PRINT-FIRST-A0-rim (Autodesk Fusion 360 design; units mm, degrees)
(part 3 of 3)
extrude "Extrude2" cut sketch "E Rear Bearing Cap Bolt seed" profile of C1 along normal blind 3 (= "capThickness")
circular_pattern "C-Pattern1" TotalAngle 360
chamfer "Chamfer1" distance 0.3 (= "bedRelief")
work_plane "WorkPlane1" AlongDistance -29 (= "hubFace - adapterThickness") ExtraOffset 0
sketch "F Adapter Flange sketch" plane through (-20.5061, -20.5061, 0) normal (0.7071, 0.7071, 0) x axis (0, 0, 1)
  circle C1 centre (0, 0) radius 38
  dimension "d967" diameter C1 = 76 (= "mountOD")
extrude "Extrude1" new body sketch "F Adapter Flange sketch" along normal blind 6 (= "adapterThickness")
work_plane "WorkPlane2" AlongDistance -23 (= "hubFace") ExtraOffset 0
sketch "F Centering Pilot sketch" plane through (-16.2635, -16.2635, 0) normal (0.7071, 0.7071, 0) x axis (0, 0, 1)
  circle C1 centre (0, 0) radius 25
  circle C2 centre (0, 0) radius 17
  dimension "d972" diameter C1 = 50 (= "pilotDiameter")
  dimension "d973" diameter C2 = 34 (= "pilotInside")
extrude "Extrude2" add sketch "F Centering Pilot sketch" along normal blind 2 (= "pilotHeight")
work_plane "WorkPlane3" AlongDistance -29 (= "hubFace - adapterThickness") ExtraOffset 0
sketch "F Shaft Clearance sketch" plane through (-20.5061, -20.5061, 0) normal (0.7071, 0.7071, 0) x axis (0, 0, 1)
  circle C1 centre (0, 0) radius 4.25
  dimension "d978" diameter C1 = 8.5 (= "shaftClearance")
extrude "Extrude3" cut sketch "F Shaft Clearance sketch" along normal blind 6 (= "adapterThickness")
work_plane "WorkPlane4" AlongDistance -29 (= "hubFace - adapterThickness") ExtraOffset 0
sketch "F Mount Holes" plane through (-20.5061, -20.5061, 0) normal (0.7071, 0.7071, 0) x axis (0, 0, 1)
  circle C1 centre (22.6274, 22.6274) radius 2.15
  circle C2 centre (-22.6274, 22.6274) radius 2.15
  circle C3 centre (-22.6274, -22.6274) radius 2.15
  circle C4 centre (22.6274, -22.6274) radius 2.15
  point P1 (0, 0)
  point P2 (22.6274, 22.6274)
  point P3 (-22.6274, 22.6274)
  point P4 (-22.6274, -22.6274)
  point P5 (22.6274, -22.6274)
  dimension "d983" distance P1 P2 = 22.6274 (= "abs(mountCircle / ( 2 * sqrt(2) ))")
  dimension "d984" distance P1 P2 = 22.6274 (= "abs(mountCircle / ( 2 * sqrt(2) ))")
  dimension "d985" diameter C1 = 4.3 (= "m4Clearance")
  dimension "d986" distance P1 P3 = 22.6274 (= "abs(-mountCircle / ( 2 * sqrt(2) ))")
  dimension "d987" distance P1 P3 = 22.6274 (= "abs(mountCircle / ( 2 * sqrt(2) ))")
  dimension "d988" diameter C2 = 4.3 (= "m4Clearance")
  dimension "d989" distance P1 P4 = 22.6274 (= "abs(-mountCircle / ( 2 * sqrt(2) ))")
  dimension "d990" distance P1 P4 = 22.6274 (= "abs(-mountCircle / ( 2 * sqrt(2) ))")
  dimension "d991" diameter C3 = 4.3 (= "m4Clearance")
  dimension "d992" distance P1 P5 = 22.6274 (= "abs(mountCircle / ( 2 * sqrt(2) ))")
  dimension "d993" distance P1 P5 = 22.6274 (= "abs(-mountCircle / ( 2 * sqrt(2) ))")
  dimension "d994" diameter C4 = 4.3 (= "m4Clearance")
extrude "Extrude4" cut sketch "F Mount Holes" along normal blind 6 (= "adapterThickness")
sketch "F Compression Sleeve Holes" plane through (-20.5061, -20.5061, 0) normal (0.7071, 0.7071, 0) x axis (0, 0, 1)
  line L1 (11.3137, 0) -> (0, 0)
  line L2 (0, 11.3137) -> (0, 0)
  line L3 (-11.3137, 0) -> (0, 0)
  line L4 (0, -11.3137) -> (0, 0)
  circle C1 centre (11.3137, 0) radius 4.1
  circle C2 centre (0, 11.3137) radius 4.1
  circle C3 centre (-11.3137, 0) radius 4.1
  circle C4 centre (0, -11.3137) radius 4.1
  point P1 (0, 0)
  point P2 (11.3137, 0)
  point P3 (0, 11.3137)
  point P5 (0, -11.3137)
  horizontal L1
  vertical L2
  horizontal L3
  vertical L4
  dimension "d997" distance P1 P2 = 11.3137 (= "abs(hubHoleSpacing / sqrt(2))")
  dimension "d998" diameter C1 = 8.2 (= "sleeveOD + sleeveAllowance")
  dimension "d999" distance P1 P3 = 11.3137 (= "abs(hubHoleSpacing / sqrt(2))")
  dimension "d1000" diameter C2 = 8.2 (= "sleeveOD + sleeveAllowance")
  dimension "d59" = 150 (= "bodyWidth")
  dimension "d1002" diameter C3 = 8.2 (= "sleeveOD + sleeveAllowance")
  dimension "d1003" distance P1 P5 = 11.3137 (= "abs(-hubHoleSpacing / sqrt(2))")
  dimension "d1004" diameter C4 = 8.2 (= "sleeveOD + sleeveAllowance")
  dimension "d1001" distance = 11.3137 (= "abs(-hubHoleSpacing / sqrt(2))")
extrude "Extrude5" cut sketch "F Compression Sleeve Holes" profile of C1 C2 C3 C4 along normal blind 6 (= "adapterThickness")
chamfer "Chamfer1" distance 0.4 (= "entryChamfer")
chamfer "Chamfer2" distance 0.3 (= "bedRelief")
work_plane "WorkPlane1" AlongDistance 0.5 (= "qFront") ExtraOffset 0
sketch "Front 608 sketch" plane through (0.3536, 0.3536, 0) normal (0.7071, 0.7071, 0) x axis (0, 0, 1)
  circle C1 centre (0, 0) radius 11
  circle C2 centre (0, 0) radius 4
  dimension "d1011" diameter C1 = 22 (= "bearingOD")
  dimension "d1012" diameter C2 = 8 (= "bearingID")
extrude "Extrude1" new body sketch "Front 608 sketch" along normal blind 7 (= "bearingWidth")
work_plane "WorkPlane2" AlongDistance 25.6 (= "qRearBearing") ExtraOffset 0
sketch "Rear 608 sketch" plane through (18.1019, 18.1019, 0) normal (0.7071, 0.7071, 0) x axis (0, 0, 1)
  circle C1 centre (0, 0) radius 11
  circle C2 centre (0, 0) radius 4
  dimension "d1017" diameter C1 = 22 (= "bearingOD")
  dimension "d1018" diameter C2 = 8 (= "bearingID")
extrude "Extrude2" new body sketch "Rear 608 sketch" along normal blind 7 (= "bearingWidth")
work_plane "WorkPlane1" AlongDistance -24 ExtraOffset 0
sketch "Metal Shaft sketch" plane through (-16.9706, -16.9706, 0) normal (0.7071, 0.7071, 0) x axis (0, 0, 1)
  circle C1 centre (0, 0) radius 4
  dimension "d1023" diameter C1 = 8
extrude "Extrude1" new body sketch "Metal Shaft sketch" along normal blind 60
work_plane "WorkPlane1" AlongDistance -3.5 (= "qFront - 4 mm") ExtraOffset 0
sketch "Front Inner Ring Spacer sketch" plane through (-2.4749, -2.4749, 0) normal (0.7071, 0.7071, 0) x axis (0, 0, 1)
  circle C1 centre (0, 0) radius 5
  circle C2 centre (0, 0) radius 4
  dimension "d1028" diameter C1 = 10
  dimension "d1029" diameter C2 = 8
extrude "Extrude1" new body sketch "Front Inner Ring Spacer sketch" along normal blind 4
work_plane "WorkPlane2" AlongDistance 7.5 (= "qFront + bearingWidth") ExtraOffset 0
sketch "Rear Inner Ring Spacer sketch" plane through (5.3033, 5.3033, 0) normal (0.7071, 0.7071, 0) x axis (0, 0, 1)
  circle C1 centre (0, 0) radius 5
  circle C2 centre (0, 0) radius 4
  dimension "d1034" diameter C1 = 10
  dimension "d1035" diameter C2 = 8
extrude "Extrude2" new body sketch "Rear Inner Ring Spacer sketch" along normal blind 4
work_plane "WorkPlane1" AlongDistance -12.5 (= "qFront - 13 mm") ExtraOffset 0
sketch "Front Collar Maximum Envelope sketch" plane through (-8.8388, -8.8388, 0) normal (0.7071, 0.7071, 0) x axis (0, 0, 1)
  circle C1 centre (0, 0) radius 11.2
  circle C2 centre (0, 0) radius 4
  dimension "d1040" diameter C1 = 22.4
  dimension "d1041" diameter C2 = 8
extrude "Extrude1" new body sketch "Front Collar Maximum Envelope sketch" along normal blind 9
work_plane "WorkPlane2" AlongDistance 11.5 (= "qFront + bearingWidth + 4 mm") ExtraOffset 0
sketch "Rear Collar Maximum Envelope sketch" plane through (8.1317, 8.1317, 0) normal (0.7071, 0.7071, 0) x axis (0, 0, 1)
  circle C1 centre (0, 0) radius 11.2
  circle C2 centre (0, 0) radius 4
  dimension "d1046" diameter C1 = 22.4
  dimension "d1047" diameter C2 = 8
extrude "Extrude2" new body sketch "Rear Collar Maximum Envelope sketch" along normal blind 9
work_plane "WorkPlane1" AlongDistance 0 ExtraOffset 0
sketch "Spacer Pattern Axis" plane through (0, 0, 0) normal (0.7071, 0.7071, 0) x axis (0, 0, 1)
  circle C1 centre (0, 0) radius 0.5
  dimension "d1052" diameter C1 = 1
work_plane "WorkPlane2" AlongDistance 10.6 (= "qFrontBack") ExtraOffset 0
sketch "Support Spacer OD" plane through (7.4953, 7.4953, 0) normal (0.7071, 0.7071, 0) x axis (0, 0, 1)
  line L1 (17, 0) -> (0, 0)
  circle C1 centre (17, 0) radius 3
  circle C2 centre (17, 0) radius 1.6
  point P1 (0, 0)
  point P2 (17, 0)
  horizontal L1
  dimension "d1055" distance P1 P2 = 17 (= "supportCircle / 2")
  dimension "d1056" diameter C1 = 6 (= "supportSpacerOD")
  dimension "d1057" diameter C2 = 3.2
extrude "Extrude1" new body sketch "Support Spacer OD" profile of C1 C2 along normal blind 12 (= "supportSpacer")
circular_pattern "C-Pattern1" TotalAngle 360
work_plane "WorkPlane1" AlongDistance -29 (= "hubFace - adapterThickness") ExtraOffset 0
sketch "Sleeve 1 Outer" plane through (-20.5061, -20.5061, 0) normal (0.7071, 0.7071, 0) x axis (0, 0, 1)
  line L1 (11.3137, 0) -> (0, 0)
  circle C1 centre (11.3137, 0) radius 4
  circle C2 centre (11.3137, 0) radius 2.15
  point P1 (0, 0)
  point P2 (11.3137, 0)
  horizontal L1
  dimension "d1064" distance P1 P2 = 11.3137 (= "abs(hubHoleSpacing / sqrt(2))")
  dimension "d1065" diameter C1 = 8 (= "sleeveOD")
  dimension "d1066" diameter C2 = 4.3
extrude "Extrude1" new body sketch "Sleeve 1 Outer" profile of C1 C2 along normal blind 6 (= "adapterThickness")
work_plane "WorkPlane2" AlongDistance -29 (= "hubFace - adapterThickness") ExtraOffset 0
sketch "Sleeve 2 Outer" plane through (-20.5061, -20.5061, 0) normal (0.7071, 0.7071, 0) x axis (0, 0, 1)
  line L1 (0, 11.3137) -> (0, 0)
  circle C1 centre (0, 11.3137) radius 4
  circle C2 centre (0, 11.3137) radius 2.15
  point P1 (0, 0)
  point P2 (0, 11.3137)
  vertical L1
  dimension "d1071" distance P1 P2 = 11.3137 (= "abs(hubHoleSpacing / sqrt(2))")
  dimension "d1072" diameter C1 = 8 (= "sleeveOD")
  dimension "d1073" diameter C2 = 4.3
extrude "Extrude2" new body sketch "Sleeve 2 Outer" profile of C1 C2 along normal blind 6 (= "adapterThickness")
work_plane "WorkPlane3" AlongDistance -29 (= "hubFace - adapterThickness") ExtraOffset 0
sketch "Sleeve 3 Outer" plane through (-20.5061, -20.5061, 0) normal (0.7071, 0.7071, 0) x axis (0, 0, 1)
  line L1 (-11.3137, 0) -> (0, 0)
  circle C1 centre (-11.3137, 0) radius 4
  circle C2 centre (-11.3137, 0) radius 2.15
  point P1 (0, 0)
  point P2 (-11.3137, 0)
  horizontal L1
  dimension "d1078" distance P1 P2 = 11.3137 (= "abs(-hubHoleSpacing / sqrt(2))")
  dimension "d1079" diameter C1 = 8 (= "sleeveOD")
  dimension "d1080" diameter C2 = 4.3
extrude "Extrude3" new body sketch "Sleeve 3 Outer" profile of C1 C2 along normal blind 6 (= "adapterThickness")
work_plane "WorkPlane4" AlongDistance -29 (= "hubFace - adapterThickness") ExtraOffset 0
sketch "Sleeve 4 Outer" plane through (-20.5061, -20.5061, 0) normal (0.7071, 0.7071, 0) x axis (0, 0, 1)
  line L1 (0, -11.3137) -> (0, 0)
  circle C1 centre (0, -11.3137) radius 4
  circle C2 centre (0, -11.3137) radius 2.15
  point P1 (0, 0)
  point P2 (0, -11.3137)
  vertical L1
  dimension "d1085" distance P1 P2 = 11.3137 (= "abs(-hubHoleSpacing / sqrt(2))")
  dimension "d1086" diameter C1 = 8 (= "sleeveOD")
  dimension "d1087" diameter C2 = 4.3
extrude "Extrude4" new body sketch "Sleeve 4 Outer" profile of C1 C2 along normal blind 6 (= "adapterThickness")
work_plane "WorkPlane1" AlongDistance -23 (= "hubFace") ExtraOffset 0
sketch "Sonic Hub Body sketch" plane through (-16.2635, -16.2635, 0) normal (0.7071, 0.7071, 0) x axis (0, 0, 1)
  circle C1 centre (0, 0) radius 16
  circle C2 centre (0, 0) radius 4
  dimension "d1092" diameter C1 = 32
  dimension "d1093" diameter C2 = 8
extrude "Extrude1" new body sketch "Sonic Hub Body sketch" along normal blind 8
work_plane "WorkPlane2" AlongDistance -15 (= "hubFace + 8 mm") ExtraOffset 0
sketch "Sonic Hub Pilot sketch" plane through (-10.6066, -10.6066, 0) normal (0.7071, 0.7071, 0) x axis (0, 0, 1)
  circle C1 centre (0, 0) radius 7
  circle C2 centre (0, 0) radius 4
  dimension "d1098" diameter C1 = 14
  dimension "d1099" diameter C2 = 8
extrude "Extrude2" add sketch "Sonic Hub Pilot sketch" along normal blind 2
work_plane "WorkPlane3" AlongDistance -23 (= "hubFace") ExtraOffset 0
sketch "Hub M4 Thread Envelopes" plane through (-16.2635, -16.2635, 0) normal (0.7071, 0.7071, 0) x axis (0, 0, 1)
  line L1 (11.3137, 0) -> (0, 0)
  line L2 (0, 11.3137) -> (0, 0)
  line L3 (-11.3137, 0) -> (0, 0)
  line L4 (0, -11.3137) -> (0, 0)
  circle C1 centre (11.3137, 0) radius 2.15
  circle C2 centre (0, 11.3137) radius 2.15
  circle C3 centre (-11.3137, 0) radius 2.15
  circle C4 centre (0, -11.3137) radius 2.15
  point P1 (0, 0)
  point P2 (11.3137, 0)
  point P3 (0, 11.3137)
  point P5 (0, -11.3137)
  horizontal L1
  vertical L2
  horizontal L3
  vertical L4
  dimension "d1104" distance P1 P2 = 11.3137 (= "abs(hubHoleSpacing / sqrt(2))")
  dimension "d1105" diameter C1 = 4.3
  dimension "d1106" distance P1 P3 = 11.3137 (= "abs(hubHoleSpacing / sqrt(2))")
  dimension "d1107" diameter C2 = 4.3
  dimension "d59" = 150 (= "bodyWidth")
  dimension "d1109" diameter C3 = 4.3
  dimension "d1110" distance P1 P5 = 11.3137 (= "abs(-hubHoleSpacing / sqrt(2))")
  dimension "d1111" diameter C4 = 4.3
  dimension "d1108" distance = 11.3137 (= "abs(-hubHoleSpacing / sqrt(2))")
extrude "Extrude3" cut sketch "Hub M4 Thread Envelopes" profile of C1 C2 C3 C4 along normal blind 8
work_plane "WorkPlane1" AlongDistance -30 (= "hubFace - adapterThickness - 1 mm") ExtraOffset 0
sketch "Hub Screw 1 Profile" plane through (-21.2132, -21.2132, 0) normal (0.7071, 0.7071, 0) x axis (0, 0, 1)
  line L1 (11.3137, 0) -> (0, 0)
  circle C1 centre (11.3137, 0) radius 2
  point P1 (0, 0)
  point P2 (11.3137, 0)
  horizontal L1
  dimension "d1116" distance P1 P2 = 11.3137 (= "abs(hubHoleSpacing / sqrt(2))")
  dimension "d1117" diameter C1 = 4
extrude "Extrude1" new body sketch "Hub Screw 1 Profile" profile of C1 along normal blind 12
work_plane "WorkPlane2" AlongDistance -34 (= "hubFace - adapterThickness - 5 mm") ExtraOffset 0
sketch "Hub Screw Head 1 Profile" plane through (-24.0416, -24.0416, 0) normal (0.7071, 0.7071, 0) x axis (0, 0, 1)
  line L1 (11.3137, 0) -> (0, 0)
  circle C1 centre (11.3137, 0) radius 3.5
  point P1 (0, 0)
  point P2 (11.3137, 0)
  horizontal L1
  dimension "d1122" distance P1 P2 = 11.3137 (= "abs(hubHoleSpacing / sqrt(2))")
  dimension "d1123" diameter C1 = 7
extrude "Extrude2" new body sketch "Hub Screw Head 1 Profile" profile of C1 along normal blind 4
work_plane "WorkPlane3" AlongDistance -30 (= "hubFace - adapterThickness - 1 mm") ExtraOffset 0
sketch "Hub Washer 1 Outer" plane through (-21.2132, -21.2132, 0) normal (0.7071, 0.7071, 0) x axis (0, 0, 1)
  line L1 (11.3137, 0) -> (0, 0)
  circle C1 centre (11.3137, 0) radius 6
  circle C2 centre (11.3137, 0) radius 2.15
  point P1 (0, 0)
  point P2 (11.3137, 0)
  horizontal L1
  dimension "d1128" distance P1 P2 = 11.3137 (= "abs(hubHoleSpacing / sqrt(2))")
  dimension "d1129" diameter C1 = 12
  dimension "d1130" diameter C2 = 4.3
extrude "Extrude3" new body sketch "Hub Washer 1 Outer" profile of C1 C2 along normal blind 1
work_plane "WorkPlane4" AlongDistance -30 (= "hubFace - adapterThickness - 1 mm") ExtraOffset 0
sketch "Hub Screw 2 Profile" plane through (-21.2132, -21.2132, 0) normal (0.7071, 0.7071, 0) x axis (0, 0, 1)
  line L1 (0, 11.3137) -> (0, 0)
  circle C1 centre (0, 11.3137) radius 2
  point P1 (0, 0)
  point P2 (0, 11.3137)
  vertical L1
  dimension "d1135" distance P1 P2 = 11.3137 (= "abs(hubHoleSpacing / sqrt(2))")
  dimension "d1136" diameter C1 = 4
extrude "Extrude4" new body sketch "Hub Screw 2 Profile" profile of C1 along normal blind 12
work_plane "WorkPlane5" AlongDistance -34 (= "hubFace - adapterThickness - 5 mm") ExtraOffset 0
sketch "Hub Screw Head 2 Profile" plane through (-24.0416, -24.0416, 0) normal (0.7071, 0.7071, 0) x axis (0, 0, 1)
  line L1 (0, 11.3137) -> (0, 0)
  circle C1 centre (0, 11.3137) radius 3.5
  point P1 (0, 0)
  point P2 (0, 11.3137)
  vertical L1
  dimension "d1141" distance P1 P2 = 11.3137 (= "abs(hubHoleSpacing / sqrt(2))")
  dimension "d1142" diameter C1 = 7
extrude "Extrude5" new body sketch "Hub Screw Head 2 Profile" profile of C1 along normal blind 4
work_plane "WorkPlane6" AlongDistance -30 (= "hubFace - adapterThickness - 1 mm") ExtraOffset 0
sketch "Hub Washer 2 Outer" plane through (-21.2132, -21.2132, 0) normal (0.7071, 0.7071, 0) x axis (0, 0, 1)
  line L1 (0, 11.3137) -> (0, 0)
  circle C1 centre (0, 11.3137) radius 6
  circle C2 centre (0, 11.3137) radius 2.15
  point P1 (0, 0)
  point P2 (0, 11.3137)
  vertical L1
  dimension "d1147" distance P1 P2 = 11.3137 (= "abs(hubHoleSpacing / sqrt(2))")
  dimension "d1148" diameter C1 = 12
  dimension "d1149" diameter C2 = 4.3
extrude "Extrude6" new body sketch "Hub Washer 2 Outer" profile of C1 C2 along normal blind 1
work_plane "WorkPlane7" AlongDistance -30 (= "hubFace - adapterThickness - 1 mm") ExtraOffset 0
sketch "Hub Screw 3 Profile" plane through (-21.2132, -21.2132, 0) normal (0.7071, 0.7071, 0) x axis (0, 0, 1)
  line L1 (-11.3137, 0) -> (0, 0)
  circle C1 centre (-11.3137, 0) radius 2
  point P1 (0, 0)
  point P2 (-11.3137, 0)
  horizontal L1
  dimension "d1154" distance P1 P2 = 11.3137 (= "abs(-hubHoleSpacing / sqrt(2))")
  dimension "d1155" diameter C1 = 4
extrude "Extrude7" new body sketch "Hub Screw 3 Profile" profile of C1 along normal blind 12
work_plane "WorkPlane8" AlongDistance -34 (= "hubFace - adapterThickness - 5 mm") ExtraOffset 0
sketch "Hub Screw Head 3 Profile" plane through (-24.0416, -24.0416, 0) normal (0.7071, 0.7071, 0) x axis (0, 0, 1)
  line L1 (-11.3137, 0) -> (0, 0)
  circle C1 centre (-11.3137, 0) radius 3.5
  point P1 (0, 0)
  point P2 (-11.3137, 0)
  horizontal L1
  dimension "d1160" distance P1 P2 = 11.3137 (= "abs(-hubHoleSpacing / sqrt(2))")
  dimension "d1161" diameter C1 = 7
extrude "Extrude8" new body sketch "Hub Screw Head 3 Profile" profile of C1 along normal blind 4
work_plane "WorkPlane9" AlongDistance -30 (= "hubFace - adapterThickness - 1 mm") ExtraOffset 0
sketch "Hub Washer 3 Outer" plane through (-21.2132, -21.2132, 0) normal (0.7071, 0.7071, 0) x axis (0, 0, 1)
  line L1 (-11.3137, 0) -> (0, 0)
  circle C1 centre (-11.3137, 0) radius 6
  circle C2 centre (-11.3137, 0) radius 2.15
  point P1 (0, 0)
  point P2 (-11.3137, 0)
  horizontal L1
  dimension "d1166" distance P1 P2 = 11.3137 (= "abs(-hubHoleSpacing / sqrt(2))")
  dimension "d1167" diameter C1 = 12
  dimension "d1168" diameter C2 = 4.3
extrude "Extrude9" new body sketch "Hub Washer 3 Outer" profile of C1 C2 along normal blind 1
work_plane "WorkPlane10" AlongDistance -30 (= "hubFace - adapterThickness - 1 mm") ExtraOffset 0
sketch "Hub Screw 4 Profile" plane through (-21.2132, -21.2132, 0) normal (0.7071, 0.7071, 0) x axis (0, 0, 1)
  line L1 (0, -11.3137) -> (0, 0)
  circle C1 centre (0, -11.3137) radius 2
  point P1 (0, 0)
  point P2 (0, -11.3137)
  vertical L1
  dimension "d1173" distance P1 P2 = 11.3137 (= "abs(-hubHoleSpacing / sqrt(2))")
  dimension "d1174" diameter C1 = 4
extrude "Extrude10" new body sketch "Hub Screw 4 Profile" profile of C1 along normal blind 12
work_plane "WorkPlane11" AlongDistance -34 (= "hubFace - adapterThickness - 5 mm") ExtraOffset 0
sketch "Hub Screw Head 4 Profile" plane through (-24.0416, -24.0416, 0) normal (0.7071, 0.7071, 0) x axis (0, 0, 1)
  line L1 (0, -11.3137) -> (0, 0)
  circle C1 centre (0, -11.3137) radius 3.5
  point P1 (0, 0)
  point P2 (0, -11.3137)
  vertical L1
  dimension "d1179" distance P1 P2 = 11.3137 (= "abs(-hubHoleSpacing / sqrt(2))")
  dimension "d1180" diameter C1 = 7
extrude "Extrude11" new body sketch "Hub Screw Head 4 Profile" profile of C1 along normal blind 4
work_plane "WorkPlane12" AlongDistance -30 (= "hubFace - adapterThickness - 1 mm") ExtraOffset 0
sketch "Hub Washer 4 Outer" plane through (-21.2132, -21.2132, 0) normal (0.7071, 0.7071, 0) x axis (0, 0, 1)
  line L1 (0, -11.3137) -> (0, 0)
  circle C1 centre (0, -11.3137) radius 6
  circle C2 centre (0, -11.3137) radius 2.15
  point P1 (0, 0)
  point P2 (0, -11.3137)
  vertical L1
  dimension "d1185" distance P1 P2 = 11.3137 (= "abs(-hubHoleSpacing / sqrt(2))")
  dimension "d1186" diameter C1 = 12
  dimension "d1187" diameter C2 = 4.3
extrude "Extrude12" new body sketch "Hub Washer 4 Outer" profile of C1 C2 along normal blind 1
work_plane "WorkPlane1" AlongDistance -30 (= "hubFace - adapterThickness - 1 mm") ExtraOffset 0
sketch "Adapter Screw 1 Profile" plane through (-21.2132, -21.2132, 0) normal (0.7071, 0.7071, 0) x axis (0, 0, 1)
  circle C1 centre (22.6274, 22.6274) radius 2
  point P1 (0, 0)
  point P2 (22.6274, 22.6274)
  dimension "d1192" distance P1 P2 = 22.6274 (= "abs(mountCircle / ( 2 * sqrt(2) ))")
  dimension "d1193" distance P1 P2 = 22.6274 (= "abs(mountCircle / ( 2 * sqrt(2) ))")
  dimension "d1194" diameter C1 = 4
extrude "Extrude1" new body sketch "Adapter Screw 1 Profile" along normal blind 30
work_plane "WorkPlane2" AlongDistance -34 (= "hubFace - adapterThickness - 5 mm") ExtraOffset 0
sketch "Adapter Screw Head 1 Profile" plane through (-24.0416, -24.0416, 0) normal (0.7071, 0.7071, 0) x axis (0, 0, 1)
  circle C1 centre (22.6274, 22.6274) radius 3.5
  point P1 (0, 0)
  point P2 (22.6274, 22.6274)
  dimension "d1199" distance P1 P2 = 22.6274 (= "abs(mountCircle / ( 2 * sqrt(2) ))")
  dimension "d1200" distance P1 P2 = 22.6274 (= "abs(mountCircle / ( 2 * sqrt(2) ))")
  dimension "d1201" diameter C1 = 7
extrude "Extrude2" new body sketch "Adapter Screw Head 1 Profile" along normal blind 4
work_plane "WorkPlane3" AlongDistance -30 (= "hubFace - adapterThickness - 1 mm") ExtraOffset 0
sketch "Adapter Washer 1 Outer" plane through (-21.2132, -21.2132, 0) normal (0.7071, 0.7071, 0) x axis (0, 0, 1)
  circle C1 centre (22.6274, 22.6274) radius 4.5
  circle C2 centre (22.6274, 22.6274) radius 2.15
  point P1 (0, 0)
  point P2 (22.6274, 22.6274)
  dimension "d1206" distance P1 P2 = 22.6274 (= "abs(mountCircle / ( 2 * sqrt(2) ))")
  dimension "d1207" distance P1 P2 = 22.6274 (= "abs(mountCircle / ( 2 * sqrt(2) ))")
  dimension "d1208" diameter C1 = 9
  dimension "d1209" diameter C2 = 4.3
extrude "Extrude3" new body sketch "Adapter Washer 1 Outer" along normal blind 1
work_plane "WorkPlane4" ExtraOffset 0
sketch "Adapter Nut Hex 1" plane through (-3.182, -3.182, 0) normal (0.7071, 0.7071, 0) x axis (0, 0, 1)
  line L1 (24.6481, 26.1274) -> (26.6689, 22.6274)
  line L2 (20.6067, 26.1274) -> (24.6481, 26.1274)
  line L3 (18.586, 22.6274) -> (20.6067, 26.1274)
  line L4 (20.6067, 19.1274) -> (18.586, 22.6274)
  line L5 (24.6481, 19.1274) -> (20.6067, 19.1274)
  line L6 (26.6689, 22.6274) -> (24.6481, 19.1274)
  circle C1 centre (22.6274, 22.6274) radius 4.0415
  point P3 (26.6689, 22.6274)
  point P4 (24.6481, 26.1274)
  point P5 (20.6067, 26.1274)
  point P6 (18.586, 22.6274)
  point P7 (20.6067, 19.1274)
  point P8 (24.6481, 19.1274)
  point P1 (0, 0)
  point P2 (22.6274, 22.6274)
  coincident C1 P3
  coincident C1 P4
  coincident C1 P5
  coincident C1 P6
  coincident C1 P7
  coincident C1 P8
  equal L1 L2
  equal L1 L3
  equal L1 L4
  equal L1 L5
  equal L1 L6
  horizontal L2
  dimension "d1214" distance P1 P2 = 22.6274 (= "abs(mountCircle / ( 2 * sqrt(2) ))")
  dimension "d1215" distance P1 P2 = 22.6274 (= "abs(mountCircle / ( 2 * sqrt(2) ))")
  dimension "d1216" diameter C1 = 8.0829 (= "2 * ( 7 mm ) / sqrt(3)")
extrude "Extrude4" new body sketch "Adapter Nut Hex 1" profile of L1 L2 L3 L4 L5 L6 along normal blind 3.2
sketch "Nut Thread Clearance 1" plane through (-3.182, -3.182, 0) normal (0.7071, 0.7071, 0) x axis (0, 0, 1)
  circle C1 centre (22.6274, 22.6274) radius 2.15
  point P1 (0, 0)
  point P2 (22.6274, 22.6274)
  dimension "d1219" distance P1 P2 = 22.6274 (= "abs(mountCircle / ( 2 * sqrt(2) ))")
  dimension "d1220" distance P1 P2 = 22.6274 (= "abs(mountCircle / ( 2 * sqrt(2) ))")
  dimension "d1221" diameter C1 = 4.3
extrude "Extrude5" cut sketch "Nut Thread Clearance 1" along normal blind 3.2
work_plane "WorkPlane5" AlongDistance -30 (= "hubFace - adapterThickness - 1 mm") ExtraOffset 0
sketch "Adapter Screw 2 Profile" plane through (-21.2132, -21.2132, 0) normal (0.7071, 0.7071, 0) x axis (0, 0, 1)
  circle C1 centre (-22.6274, 22.6274) radius 2
  point P1 (0, 0)
  point P2 (-22.6274, 22.6274)
  dimension "d1226" distance P1 P2 = 22.6274 (= "abs(-mountCircle / ( 2 * sqrt(2) ))")
  dimension "d1227" distance P1 P2 = 22.6274 (= "abs(mountCircle / ( 2 * sqrt(2) ))")
  dimension "d1228" diameter C1 = 4
extrude "Extrude6" new body sketch "Adapter Screw 2 Profile" along normal blind 30
work_plane "WorkPlane6" AlongDistance -34 (= "hubFace - adapterThickness - 5 mm") ExtraOffset 0
sketch "Adapter Screw Head 2 Profile" plane through (-24.0416, -24.0416, 0) normal (0.7071, 0.7071, 0) x axis (0, 0, 1)
  circle C1 centre (-22.6274, 22.6274) radius 3.5
  point P1 (0, 0)
  point P2 (-22.6274, 22.6274)
  dimension "d1233" distance P1 P2 = 22.6274 (= "abs(-mountCircle / ( 2 * sqrt(2) ))")
  dimension "d1234" distance P1 P2 = 22.6274 (= "abs(mountCircle / ( 2 * sqrt(2) ))")
  dimension "d1235" diameter C1 = 7
extrude "Extrude7" new body sketch "Adapter Screw Head 2 Profile" along normal blind 4
work_plane "WorkPlane7" AlongDistance -30 (= "hubFace - adapterThickness - 1 mm") ExtraOffset 0
sketch "Adapter Washer 2 Outer" plane through (-21.2132, -21.2132, 0) normal (0.7071, 0.7071, 0) x axis (0, 0, 1)
  circle C1 centre (-22.6274, 22.6274) radius 4.5
  circle C2 centre (-22.6274, 22.6274) radius 2.15
  point P1 (0, 0)
  point P2 (-22.6274, 22.6274)
  dimension "d1240" distance P1 P2 = 22.6274 (= "abs(-mountCircle / ( 2 * sqrt(2) ))")
  dimension "d1241" distance P1 P2 = 22.6274 (= "abs(mountCircle / ( 2 * sqrt(2) ))")
  dimension "d1242" diameter C1 = 9
  dimension "d1243" diameter C2 = 4.3
extrude "Extrude8" new body sketch "Adapter Washer 2 Outer" along normal blind 1
work_plane "WorkPlane8" ExtraOffset 0
sketch "Adapter Nut Hex 2" plane through (-3.182, -3.182, 0) normal (0.7071, 0.7071, 0) x axis (0, 0, 1)
  line L1 (-20.6067, 26.1274) -> (-18.586, 22.6274)
  line L2 (-24.6481, 26.1274) -> (-20.6067, 26.1274)
  line L3 (-26.6689, 22.6274) -> (-24.6481, 26.1274)
  line L4 (-24.6481, 19.1274) -> (-26.6689, 22.6274)
  line L5 (-20.6067, 19.1274) -> (-24.6481, 19.1274)
  line L6 (-18.586, 22.6274) -> (-20.6067, 19.1274)
  circle C1 centre (-22.6274, 22.6274) radius 4.0415
  point P3 (-18.586, 22.6274)
  point P4 (-20.6067, 26.1274)
  point P5 (-24.6481, 26.1274)
  point P6 (-26.6689, 22.6274)
  point P7 (-24.6481, 19.1274)
  point P8 (-20.6067, 19.1274)
  point P1 (0, 0)
  point P2 (-22.6274, 22.6274)
  coincident C1 P3
  coincident C1 P4
  coincident C1 P5
  coincident C1 P6
  coincident C1 P7
  coincident C1 P8
  equal L1 L2
  equal L1 L3
  equal L1 L4
  equal L1 L5
  equal L1 L6
  horizontal L2
  dimension "d1248" distance P1 P2 = 22.6274 (= "abs(-mountCircle / ( 2 * sqrt(2) ))")
  dimension "d1249" distance P1 P2 = 22.6274 (= "abs(mountCircle / ( 2 * sqrt(2) ))")
  dimension "d1250" diameter C1 = 8.0829 (= "2 * ( 7 mm ) / sqrt(3)")
extrude "Extrude9" new body sketch "Adapter Nut Hex 2" profile of L1 L2 L3 L4 L5 L6 along normal blind 3.2
sketch "Nut Thread Clearance 2" plane through (-3.182, -3.182, 0) normal (0.7071, 0.7071, 0) x axis (0, 0, 1)
  circle C1 centre (-22.6274, 22.6274) radius 2.15
  point P1 (0, 0)
  point P2 (-22.6274, 22.6274)
  dimension "d1253" distance P1 P2 = 22.6274 (= "abs(-mountCircle / ( 2 * sqrt(2) ))")
  dimension "d1254" distance P1 P2 = 22.6274 (= "abs(mountCircle / ( 2 * sqrt(2) ))")
  dimension "d1255" diameter C1 = 4.3
extrude "Extrude10" cut sketch "Nut Thread Clearance 2" along normal blind 3.2
work_plane "WorkPlane9" AlongDistance -30 (= "hubFace - adapterThickness - 1 mm") ExtraOffset 0
sketch "Adapter Screw 3 Profile" plane through (-21.2132, -21.2132, 0) normal (0.7071, 0.7071, 0) x axis (0, 0, 1)
  circle C1 centre (-22.6274, -22.6274) radius 2
  point P1 (0, 0)
  point P2 (-22.6274, -22.6274)
  dimension "d1260" distance P1 P2 = 22.6274 (= "abs(-mountCircle / ( 2 * sqrt(2) ))")
  dimension "d1261" distance P1 P2 = 22.6274 (= "abs(-mountCircle / ( 2 * sqrt(2) ))")
  dimension "d1262" diameter C1 = 4
extrude "Extrude11" new body sketch "Adapter Screw 3 Profile" along normal blind 30
work_plane "WorkPlane10" AlongDistance -34 (= "hubFace - adapterThickness - 5 mm") ExtraOffset 0
sketch "Adapter Screw Head 3 Profile" plane through (-24.0416, -24.0416, 0) normal (0.7071, 0.7071, 0) x axis (0, 0, 1)
  circle C1 centre (-22.6274, -22.6274) radius 3.5
  point P1 (0, 0)
  point P2 (-22.6274, -22.6274)
  dimension "d1267" distance P1 P2 = 22.6274 (= "abs(-mountCircle / ( 2 * sqrt(2) ))")
  dimension "d1268" distance P1 P2 = 22.6274 (= "abs(-mountCircle / ( 2 * sqrt(2) ))")
  dimension "d1269" diameter C1 = 7
extrude "Extrude12" new body sketch "Adapter Screw Head 3 Profile" along normal blind 4
work_plane "WorkPlane11" AlongDistance -30 (= "hubFace - adapterThickness - 1 mm") ExtraOffset 0
sketch "Adapter Washer 3 Outer" plane through (-21.2132, -21.2132, 0) normal (0.7071, 0.7071, 0) x axis (0, 0, 1)
  circle C1 centre (-22.6274, -22.6274) radius 4.5
  circle C2 centre (-22.6274, -22.6274) radius 2.15
  point P1 (0, 0)
  point P2 (-22.6274, -22.6274)
  dimension "d1274" distance P1 P2 = 22.6274 (= "abs(-mountCircle / ( 2 * sqrt(2) ))")
  dimension "d1275" distance P1 P2 = 22.6274 (= "abs(-mountCircle / ( 2 * sqrt(2) ))")
  dimension "d1276" diameter C1 = 9
  dimension "d1277" diameter C2 = 4.3
extrude "Extrude13" new body sketch "Adapter Washer 3 Outer" along normal blind 1
work_plane "WorkPlane12" ExtraOffset 0
sketch "Adapter Nut Hex 3" plane through (-3.182, -3.182, 0) normal (0.7071, 0.7071, 0) x axis (0, 0, 1)
  line L1 (-20.6067, -19.1274) -> (-18.586, -22.6274)
  line L2 (-24.6481, -19.1274) -> (-20.6067, -19.1274)
  line L3 (-26.6689, -22.6274) -> (-24.6481, -19.1274)
  line L4 (-24.6481, -26.1274) -> (-26.6689, -22.6274)
  line L5 (-20.6067, -26.1274) -> (-24.6481, -26.1274)
  line L6 (-18.586, -22.6274) -> (-20.6067, -26.1274)
  circle C1 centre (-22.6274, -22.6274) radius 4.0415
  point P3 (-18.586, -22.6274)
  point P4 (-20.6067, -19.1274)
  point P5 (-24.6481, -19.1274)
  point P6 (-26.6689, -22.6274)
  point P7 (-24.6481, -26.1274)
  point P8 (-20.6067, -26.1274)
  point P1 (0, 0)
  point P2 (-22.6274, -22.6274)
  coincident C1 P3
  coincident C1 P4
  coincident C1 P5
  coincident C1 P6
  coincident C1 P7
  coincident C1 P8
  equal L1 L2
  equal L1 L3
  equal L1 L4
  equal L1 L5
  equal L1 L6
  horizontal L2
  dimension "d1282" distance P1 P2 = 22.6274 (= "abs(-mountCircle / ( 2 * sqrt(2) ))")
  dimension "d1283" distance P1 P2 = 22.6274 (= "abs(-mountCircle / ( 2 * sqrt(2) ))")
  dimension "d1284" diameter C1 = 8.0829 (= "2 * ( 7 mm ) / sqrt(3)")
extrude "Extrude14" new body sketch "Adapter Nut Hex 3" profile of L1 L2 L3 L4 L5 L6 along normal blind 3.2
sketch "Nut Thread Clearance 3" plane through (-3.182, -3.182, 0) normal (0.7071, 0.7071, 0) x axis (0, 0, 1)
  circle C1 centre (-22.6274, -22.6274) radius 2.15
  point P1 (0, 0)
  point P2 (-22.6274, -22.6274)
  dimension "d1287" distance P1 P2 = 22.6274 (= "abs(-mountCircle / ( 2 * sqrt(2) ))")
  dimension "d1288" distance P1 P2 = 22.6274 (= "abs(-mountCircle / ( 2 * sqrt(2) ))")
  dimension "d1289" diameter C1 = 4.3
extrude "Extrude15" cut sketch "Nut Thread Clearance 3" along normal blind 3.2
work_plane "WorkPlane13" AlongDistance -30 (= "hubFace - adapterThickness - 1 mm") ExtraOffset 0
sketch "Adapter Screw 4 Profile" plane through (-21.2132, -21.2132, 0) normal (0.7071, 0.7071, 0) x axis (0, 0, 1)
  circle C1 centre (22.6274, -22.6274) radius 2
  point P1 (0, 0)
  point P2 (22.6274, -22.6274)
  dimension "d1294" distance P1 P2 = 22.6274 (= "abs(mountCircle / ( 2 * sqrt(2) ))")
  dimension "d1295" distance P1 P2 = 22.6274 (= "abs(-mountCircle / ( 2 * sqrt(2) ))")
  dimension "d1296" diameter C1 = 4
extrude "Extrude16" new body sketch "Adapter Screw 4 Profile" along normal blind 30
work_plane "WorkPlane14" AlongDistance -34 (= "hubFace - adapterThickness - 5 mm") ExtraOffset 0
sketch "Adapter Screw Head 4 Profile" plane through (-24.0416, -24.0416, 0) normal (0.7071, 0.7071, 0) x axis (0, 0, 1)
  circle C1 centre (22.6274, -22.6274) radius 3.5
  point P1 (0, 0)
  point P2 (22.6274, -22.6274)
  dimension "d1301" distance P1 P2 = 22.6274 (= "abs(mountCircle / ( 2 * sqrt(2) ))")
  dimension "d1302" distance P1 P2 = 22.6274 (= "abs(-mountCircle / ( 2 * sqrt(2) ))")
  dimension "d1303" diameter C1 = 7
extrude "Extrude17" new body sketch "Adapter Screw Head 4 Profile" along normal blind 4
work_plane "WorkPlane15" AlongDistance -30 (= "hubFace - adapterThickness - 1 mm") ExtraOffset 0
sketch "Adapter Washer 4 Outer" plane through (-21.2132, -21.2132, 0) normal (0.7071, 0.7071, 0) x axis (0, 0, 1)
  circle C1 centre (22.6274, -22.6274) radius 4.5
  circle C2 centre (22.6274, -22.6274) radius 2.15
  point P1 (0, 0)
  point P2 (22.6274, -22.6274)
  dimension "d1308" distance P1 P2 = 22.6274 (= "abs(mountCircle / ( 2 * sqrt(2) ))")
  dimension "d1309" distance P1 P2 = 22.6274 (= "abs(-mountCircle / ( 2 * sqrt(2) ))")
  dimension "d1310" diameter C1 = 9
  dimension "d1311" diameter C2 = 4.3
extrude "Extrude18" new body sketch "Adapter Washer 4 Outer" along normal blind 1
work_plane "WorkPlane16" ExtraOffset 0
sketch "Adapter Nut Hex 4" plane through (-3.182, -3.182, 0) normal (0.7071, 0.7071, 0) x axis (0, 0, 1)
  line L1 (24.6481, -19.1274) -> (26.6689, -22.6274)
  line L2 (20.6067, -19.1274) -> (24.6481, -19.1274)
  line L3 (18.586, -22.6274) -> (20.6067, -19.1274)
  line L4 (20.6067, -26.1274) -> (18.586, -22.6274)
  line L5 (24.6481, -26.1274) -> (20.6067, -26.1274)
  line L6 (26.6689, -22.6274) -> (24.6481, -26.1274)
  circle C1 centre (22.6274, -22.6274) radius 4.0415
  point P3 (26.6689, -22.6274)
  point P4 (24.6481, -19.1274)
  point P5 (20.6067, -19.1274)
  point P6 (18.586, -22.6274)
  point P7 (20.6067, -26.1274)
  point P8 (24.6481, -26.1274)
  point P1 (0, 0)
  point P2 (22.6274, -22.6274)
  coincident C1 P3
  coincident C1 P4
  coincident C1 P5
  coincident C1 P6
  coincident C1 P7
  coincident C1 P8
  equal L1 L2
  equal L1 L3
  equal L1 L4
  equal L1 L5
  equal L1 L6
  horizontal L2
  dimension "d1316" distance P1 P2 = 22.6274 (= "abs(mountCircle / ( 2 * sqrt(2) ))")
  dimension "d1317" distance P1 P2 = 22.6274 (= "abs(-mountCircle / ( 2 * sqrt(2) ))")
  dimension "d1318" diameter C1 = 8.0829 (= "2 * ( 7 mm ) / sqrt(3)")
extrude "Extrude19" new body sketch "Adapter Nut Hex 4" profile of L1 L2 L3 L4 L5 L6 along normal blind 3.2
sketch "Nut Thread Clearance 4" plane through (-3.182, -3.182, 0) normal (0.7071, 0.7071, 0) x axis (0, 0, 1)
  circle C1 centre (22.6274, -22.6274) radius 2.15
  point P1 (0, 0)
  point P2 (22.6274, -22.6274)
  dimension "d1321" distance P1 P2 = 22.6274 (= "abs(mountCircle / ( 2 * sqrt(2) ))")
  dimension "d1322" distance P1 P2 = 22.6274 (= "abs(-mountCircle / ( 2 * sqrt(2) ))")
  dimension "d1323" diameter C1 = 4.3
extrude "Extrude20" cut sketch "Nut Thread Clearance 4" along normal blind 3.2
work_plane "WorkPlane1" AlongDistance 0 ExtraOffset 0
sketch "M3 Pattern Axis" plane through (0, 0, 0) normal (0.7071, 0.7071, 0) x axis (0, 0, 1)
  circle C1 centre (0, 0) radius 0.5
  dimension "d1328" diameter C1 = 1
work_plane "WorkPlane2" AlongDistance -8.7 (= "qRearEnd + capThickness + 0.5 mm - 45 mm") ExtraOffset 0
sketch "M3 Shank Profile" plane through (-6.1518, -6.1518, 0) normal (0.7071, 0.7071, 0) x axis (0, 0, 1)
  line L1 (17, 0) -> (0, 0)
  circle C1 centre (17, 0) radius 1.5
  point P1 (0, 0)
  point P2 (17, 0)
  horizontal L1
  dimension "d1331" distance P1 P2 = 17 (= "supportCircle / 2")
  dimension "d1332" diameter C1 = 3
extrude "Extrude1" new body sketch "M3 Shank Profile" profile of C1 along normal blind 45
work_plane "WorkPlane3" AlongDistance 36.3 (= "qRearEnd + capThickness + 0.5 mm") ExtraOffset 0
sketch "M3 Head Profile" plane through (25.668, 25.668, 0) normal (0.7071, 0.7071, 0) x axis (0, 0, 1)
  line L1 (17, 0) -> (0, 0)
  circle C1 centre (17, 0) radius 2.75
  point P1 (0, 0)
  point P2 (17, 0)
  horizontal L1
  dimension "d1337" distance P1 P2 = 17 (= "supportCircle / 2")
  dimension "d1338" diameter C1 = 5.5
extrude "Extrude2" new body sketch "M3 Head Profile" profile of C1 along normal blind 3
work_plane "WorkPlane4" AlongDistance 35.8 (= "qRearEnd + capThickness") ExtraOffset 0
sketch "Rear M3 Washer Profile" plane through (25.3144, 25.3144, 0) normal (0.7071, 0.7071, 0) x axis (0, 0, 1)
  line L1 (17, 0) -> (0, 0)
  circle C1 centre (17, 0) radius 3.5
  circle C2 centre (17, 0) radius 1.65
  point P1 (0, 0)
  point P2 (17, 0)
  horizontal L1
  dimension "d1343" distance P1 P2 = 17 (= "supportCircle / 2")
  dimension "d1344" diameter C1 = 7
  dimension "d1345" diameter C2 = 3.3
extrude "Extrude3" new body sketch "Rear M3 Washer Profile" profile of C1 C2 along normal blind 0.5
work_plane "WorkPlane5" AlongDistance -3 (= "qFront - capThickness - 0.5 mm") ExtraOffset 0
sketch "Front M3 Washer Profile" plane through (-2.1213, -2.1213, 0) normal (0.7071, 0.7071, 0) x axis (0, 0, 1)
  line L1 (17, 0) -> (0, 0)
  circle C1 centre (17, 0) radius 3.5
  circle C2 centre (17, 0) radius 1.65
  point P1 (0, 0)
  point P2 (17, 0)
  horizontal L1
  dimension "d1350" distance P1 P2 = 17 (= "supportCircle / 2")
  dimension "d1351" diameter C1 = 7
  dimension "d1352" diameter C2 = 3.3
extrude "Extrude4" new body sketch "Front M3 Washer Profile" profile of C1 C2 along normal blind 0.5
work_plane "WorkPlane6" AlongDistance -7 (= "qFront - capThickness - 4.5 mm") ExtraOffset 0
sketch "Front M3 Nyloc Envelope Profile" plane through (-4.9497, -4.9497, 0) normal (0.7071, 0.7071, 0) x axis (0, 0, 1)
  line L1 (17, 0) -> (0, 0)
  circle C1 centre (17, 0) radius 3.18
  circle C2 centre (17, 0) radius 1.65
  point P1 (0, 0)
  point P2 (17, 0)
  horizontal L1
  dimension "d1357" distance P1 P2 = 17 (= "supportCircle / 2")
  dimension "d1358" diameter C1 = 6.36
  dimension "d1359" diameter C2 = 3.3
extrude "Extrude5" new body sketch "Front M3 Nyloc Envelope Profile" profile of C1 C2 along normal blind 4
circular_pattern "C-Pattern1" TotalAngle 360
work_plane "WorkPlane25" RotateAngle 90 ExtraOffset 0
work_plane "WorkPlane26" AlongDistance 75 (= "bodyWidth / 2") ExtraOffset 0
sketch "B Driver Pad 1 Slot" plane through (0, -75, 0) normal (0, -1, 0) x axis (-1, 0, 0)
  line L1 (49.5, 16.6274) -> (43, 16.6274)
  line L2 (43, 28.6274) -> (49.5, 28.6274)
  line L3 (49.5, 22.6274) -> (43, 22.6274)
  arc A1 centre (49.5, 22.6274) radius 6 clockwise from (49.5, 28.6274) to (49.5, 16.6274)
  arc A2 centre (43, 22.6274) radius 6 clockwise from (43, 16.6274) to (43, 28.6274)
  point P2 (43, 22.6274)
  point P7 (43, 22.6274)
  point P1 (0, 0)
  point P8 (49.5, 22.6274)
  coincident P2 P7
  tangent L1 A1
  tangent A1 L2
  tangent L2 A2
  tangent L1 A2
  parallel L1 L2
  horizontal L3
  dimension "d1371" distance P1 P2 = 43 (= "Linear Dimension-2")
  dimension "d1372" distance P1 P2 = 22.6274 (= "Linear Dimension-3")
  dimension "d1373" diameter A1 = 12
  dimension "d1374" distance P7 P8 = 6.5
extrude "Extrude44" add sketch "B Driver Pad 1 Slot" profile of L1 A1 L2 A2 no distance stored
sketch "B Driver Pad 2 Slot" plane through (0, -75, 0) normal (0, -1, 0) x axis (-1, 0, 0)
  line L1 (49.5, -28.6274) -> (43, -28.6274)
  line L2 (43, -16.6274) -> (49.5, -16.6274)
  line L3 (49.5, -22.6274) -> (43, -22.6274)
  arc A1 centre (49.5, -22.6274) radius 6 clockwise from (49.5, -16.6274) to (49.5, -28.6274)
  arc A2 centre (43, -22.6274) radius 6 clockwise from (43, -28.6274) to (43, -16.6274)
  point P2 (43, -22.6274)
  point P7 (43, -22.6274)
  point P1 (0, 0)
  point P8 (49.5, -22.6274)
  coincident P2 P7
  tangent L1 A1
  tangent A1 L2
  tangent L2 A2
  tangent L1 A2
  parallel L1 L2
  horizontal L3
  dimension "d1377" distance P1 P2 = 43 (= "Linear Dimension-2")
  dimension "d1378" distance P1 P2 = 22.6274 (= "Linear Dimension-3")
  dimension "d1379" diameter A1 = 12
  dimension "d1380" distance P7 P8 = 6.5
extrude "Extrude45" add sketch "B Driver Pad 2 Slot" profile of L1 A1 L2 A2 no distance stored
sketch "B Driver Pad 3 Slot" plane through (0, -75, 0) normal (0, -1, 0) x axis (-1, 0, 0)
  line L1 (113.5, -28.6274) -> (107, -28.6274)
  line L2 (107, -16.6274) -> (113.5, -16.6274)
  line L3 (113.5, -22.6274) -> (107, -22.6274)
  arc A1 centre (113.5, -22.6274) radius 6 clockwise from (113.5, -16.6274) to (113.5, -28.6274)
  arc A2 centre (107, -22.6274) radius 6 clockwise from (107, -28.6274) to (107, -16.6274)
  point P2 (107, -22.6274)
  point P7 (107, -22.6274)
  point P1 (0, 0)
  point P8 (113.5, -22.6274)
  coincident P2 P7
  tangent L1 A1
  tangent A1 L2
  tangent L2 A2
  tangent L1 A2
  parallel L1 L2
  horizontal L3
  dimension "d1383" distance P1 P2 = 107 (= "Linear Dimension-2")
  dimension "d1384" distance P1 P2 = 22.6274 (= "Linear Dimension-3")
  dimension "d1385" diameter A1 = 12
  dimension "d1386" distance P7 P8 = 6.5
extrude "Extrude46" add sketch "B Driver Pad 3 Slot" profile of L1 A1 L2 A2 no distance stored
sketch "B Driver Pad 4 Slot" plane through (0, -75, 0) normal (0, -1, 0) x axis (-1, 0, 0)
  line L1 (113.5, 16.6274) -> (107, 16.6274)
  line L2 (107, 28.6274) -> (113.5, 28.6274)
  line L3 (113.5, 22.6274) -> (107, 22.6274)
  arc A1 centre (113.5, 22.6274) radius 6 clockwise from (113.5, 28.6274) to (113.5, 16.6274)
  arc A2 centre (107, 22.6274) radius 6 clockwise from (107, 16.6274) to (107, 28.6274)
  point P2 (107, 22.6274)
  point P7 (107, 22.6274)
  point P1 (0, 0)
  point P8 (113.5, 22.6274)
  coincident P2 P7
  tangent L1 A1
  tangent A1 L2
  tangent L2 A2
  tangent L1 A2
  parallel L1 L2
  horizontal L3
  dimension "d1389" distance P1 P2 = 107 (= "Linear Dimension-2")
  dimension "d1390" distance P1 P2 = 22.6274 (= "Linear Dimension-3")
  dimension "d1391" diameter A1 = 12
  dimension "d1392" distance P7 P8 = 6.5
extrude "Extrude47" add sketch "B Driver Pad 4 Slot" profile of L1 A1 L2 A2 no distance stored
work_plane "WorkPlane27" AlongDistance -35 ExtraOffset 0
sketch "B Mount Driver Axes" plane through (-24.7487, -24.7487, 0) normal (0.7071, 0.7071, 0) x axis (0, 0, 1)
  circle C1 centre (22.6274, 22.6274) radius 2.5
  circle C2 centre (-22.6274, 22.6274) radius 2.5
  circle C3 centre (-22.6274, -22.6274) radius 2.5
  circle C4 centre (22.6274, -22.6274) radius 2.5
  point P1 (0, 0)
  point P2 (22.6274, 22.6274)
  point P3 (-22.6274, 22.6274)
  point P4 (-22.6274, -22.6274)
  point P5 (22.6274, -22.6274)
  dimension "d1397" distance P1 P2 = 22.6274 (= "abs(mountCircle / ( 2 * sqrt(2) ))")
  dimension "d1398" distance P1 P2 = 22.6274 (= "abs(mountCircle / ( 2 * sqrt(2) ))")
  dimension "d1399" diameter C1 = 5 (= "driverPort")
  dimension "d1400" distance P1 P3 = 22.6274 (= "abs(-mountCircle / ( 2 * sqrt(2) ))")
  dimension "d1401" distance P1 P3 = 22.6274 (= "abs(mountCircle / ( 2 * sqrt(2) ))")
  dimension "d1402" diameter C2 = 5 (= "driverPort")
  dimension "d1403" distance P1 P4 = 22.6274 (= "abs(-mountCircle / ( 2 * sqrt(2) ))")
  dimension "d1404" distance P1 P4 = 22.6274 (= "abs(-mountCircle / ( 2 * sqrt(2) ))")
  dimension "d1405" diameter C3 = 5 (= "driverPort")
  dimension "d1406" distance P1 P5 = 22.6274 (= "abs(mountCircle / ( 2 * sqrt(2) ))")
  dimension "d1407" distance P1 P5 = 22.6274 (= "abs(-mountCircle / ( 2 * sqrt(2) ))")
  dimension "d1408" diameter C4 = 5 (= "driverPort")
extrude "Extrude48" cut sketch "B Mount Driver Axes" no distance stored
ground "Pin"
as_built_joint "As-built1" RotateMinimum 0 RotateMaximum 180
as_built_joint "As-built2"
as_built_joint "As-built3"
as_built_joint "As-built4"
as_built_joint "As-built5"
as_built_joint "As-built6"
as_built_joint "As-built7"
as_built_joint "As-built8"
as_built_joint "As-built9"
as_built_joint "As-built10"
as_built_joint "As-built11"
as_built_joint "As-built12"
as_built_joint "As-built13"
as_built_joint "As-built14"
as_built_joint "As-built15"
work_plane "WorkPlane33" AlongDistance -35 ExtraOffset 0
sketch "PRINT-FIRST-A0-rim Crop Footprint" plane through (0, 0, -35) normal (0, 0, 1) x axis (1, 0, 0)
  line L1 (130, 66.5) -> (55, 66.5)
  line L2 (130, 75) -> (130, 66.5)
  line L3 (55, 75) -> (130, 75)
  line L4 (55, 66.5) -> (55, 75)
  point P1 (0, 0)
  point P2 (55, 66.5)
  point P3 (130, 66.5)
  point P4 (130, 75)
  point P5 (55, 75)
  dimension "d1451" distance P1 P2 = 55 (= "abs(55 mm)")
  dimension "d1452" distance P1 P2 = 66.5 (= "abs(66.5 mm)")
  dimension "d1453" distance P1 P3 = 130 (= "abs(130 mm)")
  dimension "d1454" distance P1 P3 = 66.5 (= "abs(66.5 mm)")
  dimension "d1455" distance P1 P4 = 130 (= "abs(130 mm)")
  dimension "d1456" distance P1 P4 = 75 (= "abs(75 mm)")
  dimension "d1457" distance P1 P5 = 55 (= "abs(55 mm)")
  dimension "d1458" distance P1 P5 = 75 (= "abs(75 mm)")
extrude "Extrude46" sketch "PRINT-FIRST-A0-rim Crop Footprint" along normal blind 70
work_plane "WorkPlane34" AlongDistance 90.1 ExtraOffset 0
sketch "PRINT-FIRST-A0-rim Level Bed Boundary" plane through (63.7103, 63.7103, 0) normal (0.7071, 0.7071, 0) x axis (0, 0, 1)
  line L1 (200, -200) -> (-200, -200)
  line L2 (200, 200) -> (200, -200)
  line L3 (-200, 200) -> (200, 200)
  line L4 (-200, -200) -> (-200, 200)
  line L5 (200, 200) -> (-200, -200)
  point P1 (0, 0)
  point P2 (-200, -200)
  point P3 (200, -200)
  point P4 (200, 200)
  horizontal L1
  vertical L2
  horizontal L3
  vertical L4
  midpoint P1 L5
  dimension "d1463" distance P2 P3 = 400
  dimension "d1464" distance P3 P4 = 400
extrude "Extrude47" sketch "PRINT-FIRST-A0-rim Level Bed Boundary" profile of L1 L2 L3 L4 along normal blind 300
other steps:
base_feature "Base Feature1" bodies "A Housing print"
base_feature "Base Feature1" bodies "B Moving Body print"
create_component "CreateComponent1"
reparent_decal "ReparentDecal1"
remove_body "RemoveBody1"
create_component "CreateComponent2"
reparent_decal "ReparentDecal2"
remove_body "RemoveBody2"
create_component "CreateComponent3"
create_component "CreateComponent4"
create_component "CreateComponent5"
create_component "CreateComponent6"
create_component "CreateComponent7"
create_component "CreateComponent8"
create_component "CreateComponent9"
create_component "CreateComponent10"
create_component "CreateComponent11"
create_component "CreateComponent12"
create_component "CreateComponent13"
create_component "CreateComponent14"
create_component "CreateComponent15"
create_component "CreateComponent16"
named bodies: "A Housing print", "B Moving Body print"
